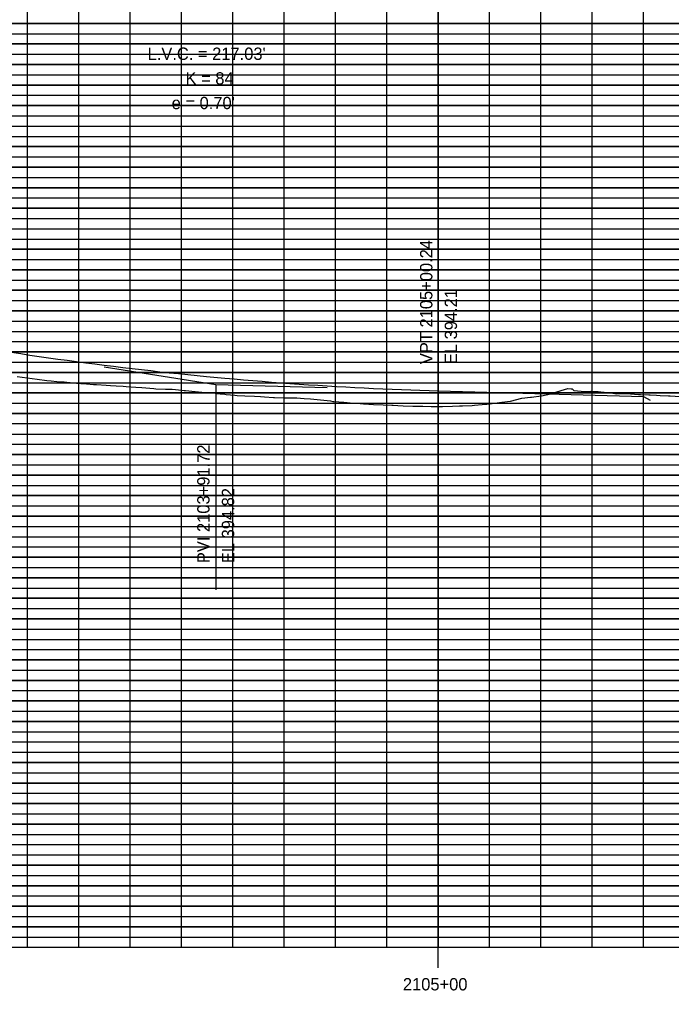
# Model space of a CAD drawing. Extents: x 1195880 to 1289360, y 2059330 to 2086925.
# Drawn here: x 1197268.9 to 1197586.5, y 2066770.1 to 2067243.1 of the extents above; entities that cross this region are included whole.
import ezdxf

# ---------------------------------------------------------------- set-up
doc = ezdxf.new("R2010")
doc.units = 0
for name, color, linetype in [('Clip', 7, 'Continuous'), ('Default', 7, 'Continuous'), ('Existing Ground PGL', 7, 'Continuous'), ('Grid', 7, 'Continuous'), ('Grid Lables', 7, 'Continuous'), ('Profile', 7, 'Continuous'), ('Profile Annotation', 7, 'Continuous')]:
    doc.layers.add(name, color=color, linetype=linetype)

msp = doc.modelspace()

# ---------------------------------------------------------------- linework, layer by layer
at = {"layer": 'Clip'}
msp.add_lwpolyline([(1197072.8, 2066891.15), (1197672.8, 2066891.15), (1197672.8, 2067241.15), (1197072.8, 2067241.15)], close=True, dxfattribs=at)
at = {"layer": 'Default'}
for p, q in [((1197473.04, 2066791.15), (1197473.04, 2067414.26)), ((1197572.8, 2066791.15), (1197572.8, 2067060.45)), ((1197572.8, 2067059.39), (1197576.01, 2067057.62)), ((1197472.8, 2066791.15), (1197473.04, 2066791.15)), ((1197472.8, 2066791.15), (1197572.8, 2066791.15))]:
    msp.add_line(p, q, dxfattribs=at)
at = {"layer": 'Existing Ground PGL'}
for points in [[(1197267.87, 2067069.12), (1197270.26, 2067068.88), (1197272.69, 2067068.53), (1197277.51, 2067067.88), (1197282.32, 2067067.26), (1197284.46, 2067067), (1197287.14, 2067066.79), (1197290.73, 2067066.52), (1197291.96, 2067066.41), (1197296.78, 2067066), (1197298.81, 2067065.84), (1197301.59, 2067065.59), (1197305.08, 2067065.3), (1197306.41, 2067065.21), (1197311.23, 2067064.91), (1197313.26, 2067064.79), (1197316.04, 2067064.61), (1197319.54, 2067064.4), (1197320.86, 2067064.31), (1197325.68, 2067064.02), (1197328.62, 2067063.87), (1197330.5, 2067063.66), (1197334.32, 2067063.26), (1197335.31, 2067063.21), (1197340.13, 2067063.03), (1197343.31, 2067062.94), (1197344.95, 2067062.79), (1197349.21, 2067062.43), (1197349.76, 2067062.37), (1197354.58, 2067061.87), (1197359.4, 2067061.41), (1197364.22, 2067060.98), (1197364.48, 2067060.95), (1197369.03, 2067060.5), (1197369.67, 2067060.44), (1197373.85, 2067060.05), (1197374.96, 2067059.95), (1197378.67, 2067059.78), (1197383.48, 2067059.6), (1197386.3, 2067059.51), (1197388.3, 2067059.32), (1197392.67, 2067058.95), (1197393.12, 2067058.94), (1197397.94, 2067058.84), (1197402.75, 2067058.78), (1197403.99, 2067058.77), (1197407.57, 2067058.54), (1197410.75, 2067058.35), (1197412.39, 2067058.17), (1197417.2, 2067057.67), (1197420.44, 2067057.35), (1197421.64, 2067057.06), (1197422.02, 2067057.02), (1197426.84, 2067056.61), (1197431.66, 2067056.22), (1197433.22, 2067056.11), (1197436.47, 2067055.86), (1197436.81, 2067055.84), (1197441.29, 2067055.59), (1197446.11, 2067055.36), (1197450.22, 2067055.18), (1197450.93, 2067055.14), (1197453.14, 2067055.04), (1197455.74, 2067054.9), (1197455.85, 2067054.9), (1197460.56, 2067054.76), (1197465.38, 2067054.65), (1197469.44, 2067054.58), (1197470.19, 2067054.56), (1197472.06, 2067054.51), (1197475.01, 2067054.59), (1197479.83, 2067054.74), (1197483.25, 2067054.88), (1197484.21, 2067054.81), (1197484.65, 2067054.83), (1197489.46, 2067055.13), (1197490.54, 2067055.2), (1197494.28, 2067055.55), (1197496.48, 2067055.77), (1197496.52, 2067055.77), (1197496.55, 2067055.78), (1197496.61, 2067055.78), (1197496.68, 2067055.79), (1197496.75, 2067055.8), (1197496.83, 2067055.8), (1197496.91, 2067055.81), (1197496.99, 2067055.82), (1197497.09, 2067055.83), (1197497.14, 2067055.84), (1197497.19, 2067055.84), (1197497.28, 2067055.85), (1197497.39, 2067055.86), (1197497.51, 2067055.87), (1197497.53, 2067055.87), (1197497.63, 2067055.88), (1197497.73, 2067055.89), (1197497.8, 2067055.9), (1197497.9, 2067055.91), (1197498.05, 2067055.92), (1197498.12, 2067055.93), (1197498.21, 2067055.94), (1197499.1, 2067056.05), (1197503.91, 2067056.66), (1197508.09, 2067057.2)], [(1197508.09, 2067057.2), (1197513.55, 2067058.59), (1197517.85, 2067059.08), (1197518.37, 2067059.15), (1197522.97, 2067059.75), (1197523.18, 2067059.8), (1197527.75, 2067060.81), (1197528, 2067060.89), (1197532.82, 2067062.38), (1197535.99, 2067063.36), (1197537.63, 2067063.24), (1197538.08, 2067063.21), (1197538.92, 2067062.41), (1197542.45, 2067062.08), (1197544.53, 2067061.88), (1197547.27, 2067061.98), (1197547.39, 2067061.98), (1197550.81, 2067061.8), (1197552.09, 2067061.67), (1197556.9, 2067061.17), (1197557.13, 2067061.15), (1197559.66, 2067060.78), (1197561.72, 2067060.84), (1197562.87, 2067060.88), (1197566.54, 2067060.69), (1197570.37, 2067060.49), (1197571.35, 2067060.45), (1197575.36, 2067060.27), (1197576.17, 2067060.22), (1197579.16, 2067060.03), (1197580.99, 2067059.95), (1197584.95, 2067059.79), (1197585.81, 2067059.75), (1197590.62, 2067059.51)]]:
    msp.add_lwpolyline(points, dxfattribs=at)
at = {"layer": 'Grid'}
for p, q in [((1197272.8, 2066791.15), (1197272.8, 2067391.15)), ((1197297.8, 2066791.15), (1197297.8, 2067391.15)), ((1197322.8, 2066791.15), (1197322.8, 2067391.15)), ((1197347.8, 2066791.15), (1197347.8, 2067391.15)), ((1197372.8, 2066791.15), (1197372.8, 2067391.15)), ((1197397.8, 2066791.15), (1197397.8, 2067391.15)), ((1197422.8, 2066791.15), (1197422.8, 2067391.15)), ((1197447.8, 2066791.15), (1197447.8, 2067391.15)), ((1197472.8, 2066791.15), (1197472.8, 2067391.15)), ((1197497.8, 2066791.15), (1197497.8, 2067391.15)), ((1197522.8, 2066791.15), (1197522.8, 2067391.15)), ((1197547.8, 2066791.15), (1197547.8, 2067391.15)), ((1197572.8, 2066791.15), (1197572.8, 2067391.15)), ((1196972.8, 2067241.15), (1197972.8, 2067241.15)), ((1196972.8, 2067236.15), (1197972.8, 2067236.15)), ((1196972.8, 2067231.15), (1197972.8, 2067231.15)), ((1197972.8, 2067231.15), (1196972.8, 2067231.15)), ((1196972.8, 2067226.15), (1197972.8, 2067226.15)), ((1196972.8, 2067221.15), (1197972.8, 2067221.15)), ((1197972.8, 2067221.15), (1196972.8, 2067221.15)), ((1196972.8, 2067216.15), (1197972.8, 2067216.15)), ((1196972.8, 2067211.15), (1197972.8, 2067211.15)), ((1197972.8, 2067211.15), (1196972.8, 2067211.15)), ((1196972.8, 2067206.15), (1197972.8, 2067206.15)), ((1196972.8, 2067201.15), (1197972.8, 2067201.15)), ((1197972.8, 2067201.15), (1196972.8, 2067201.15)), ((1196972.8, 2067196.15), (1197972.8, 2067196.15)), ((1196972.8, 2067191.15), (1197972.8, 2067191.15)), ((1196972.8, 2067186.15), (1197972.8, 2067186.15)), ((1196972.8, 2067181.15), (1197972.8, 2067181.15)), ((1197972.8, 2067181.15), (1196972.8, 2067181.15)), ((1196972.8, 2067176.15), (1197972.8, 2067176.15)), ((1196972.8, 2067171.15), (1197972.8, 2067171.15)), ((1197972.8, 2067171.15), (1196972.8, 2067171.15)), ((1196972.8, 2067166.15), (1197972.8, 2067166.15)), ((1196972.8, 2067161.15), (1197972.8, 2067161.15)), ((1197972.8, 2067161.15), (1196972.8, 2067161.15)), ((1196972.8, 2067156.15), (1197972.8, 2067156.15)), ((1196972.8, 2067151.15), (1197972.8, 2067151.15)), ((1197972.8, 2067151.15), (1196972.8, 2067151.15)), ((1196972.8, 2067146.15), (1197972.8, 2067146.15)), ((1196972.8, 2067141.15), (1197972.8, 2067141.15)), ((1196972.8, 2067136.15), (1197972.8, 2067136.15)), ((1196972.8, 2067131.15), (1197972.8, 2067131.15)), ((1197972.8, 2067131.15), (1196972.8, 2067131.15)), ((1196972.8, 2067126.15), (1197972.8, 2067126.15)), ((1196972.8, 2067121.15), (1197972.8, 2067121.15)), ((1197972.8, 2067121.15), (1196972.8, 2067121.15)), ((1196972.8, 2067116.15), (1197972.8, 2067116.15)), ((1196972.8, 2067111.15), (1197972.8, 2067111.15)), ((1197972.8, 2067111.15), (1196972.8, 2067111.15)), ((1196972.8, 2067106.15), (1197972.8, 2067106.15)), ((1196972.8, 2067101.15), (1197972.8, 2067101.15)), ((1197972.8, 2067101.15), (1196972.8, 2067101.15)), ((1196972.8, 2067096.15), (1197972.8, 2067096.15)), ((1196972.8, 2067091.15), (1197972.8, 2067091.15)), ((1196972.8, 2067086.15), (1197972.8, 2067086.15)), ((1196972.8, 2067081.15), (1197972.8, 2067081.15)), ((1197972.8, 2067081.15), (1196972.8, 2067081.15)), ((1196972.8, 2067076.15), (1197972.8, 2067076.15)), ((1196972.8, 2067071.15), (1197972.8, 2067071.15)), ((1197972.8, 2067071.15), (1196972.8, 2067071.15)), ((1196972.8, 2067066.15), (1197972.8, 2067066.15)), ((1196972.8, 2067061.15), (1197972.8, 2067061.15)), ((1197972.8, 2067061.15), (1196972.8, 2067061.15)), ((1196972.8, 2067056.15), (1197972.8, 2067056.15)), ((1196972.8, 2067051.15), (1197972.8, 2067051.15)), ((1197972.8, 2067051.15), (1196972.8, 2067051.15)), ((1197972.8, 2067046.15), (1196972.8, 2067046.15)), ((1196972.8, 2067041.15), (1197972.8, 2067041.15)), ((1196972.8, 2067036.15), (1197972.8, 2067036.15)), ((1196972.8, 2067031.15), (1197972.8, 2067031.15)), ((1197972.8, 2067031.15), (1196972.8, 2067031.15)), ((1196972.8, 2067026.15), (1197972.8, 2067026.15)), ((1196972.8, 2067021.15), (1197972.8, 2067021.15)), ((1197972.8, 2067021.15), (1196972.8, 2067021.15)), ((1196972.8, 2067016.15), (1197972.8, 2067016.15)), ((1196972.8, 2067011.15), (1197972.8, 2067011.15)), ((1197972.8, 2067011.15), (1196972.8, 2067011.15)), ((1196972.8, 2067006.15), (1197972.8, 2067006.15)), ((1196972.8, 2067001.15), (1197972.8, 2067001.15)), ((1197972.8, 2067001.15), (1196972.8, 2067001.15)), ((1196972.8, 2066996.15), (1197972.8, 2066996.15)), ((1196972.8, 2066991.15), (1197972.8, 2066991.15)), ((1196972.8, 2066986.15), (1197972.8, 2066986.15)), ((1196972.8, 2066981.15), (1197972.8, 2066981.15)), ((1197972.8, 2066981.15), (1196972.8, 2066981.15)), ((1196972.8, 2066976.15), (1197972.8, 2066976.15)), ((1196972.8, 2066971.15), (1197972.8, 2066971.15)), ((1197972.8, 2066971.15), (1196972.8, 2066971.15)), ((1196972.8, 2066966.15), (1197972.8, 2066966.15)), ((1196972.8, 2066961.15), (1197972.8, 2066961.15)), ((1197972.8, 2066961.15), (1196972.8, 2066961.15)), ((1196972.8, 2066956.15), (1197972.8, 2066956.15)), ((1196972.8, 2066951.15), (1197972.8, 2066951.15)), ((1197972.8, 2066951.15), (1196972.8, 2066951.15)), ((1196972.8, 2066946.15), (1197972.8, 2066946.15)), ((1196972.8, 2066941.15), (1197972.8, 2066941.15)), ((1196972.8, 2066936.15), (1197972.8, 2066936.15)), ((1196972.8, 2066931.15), (1197972.8, 2066931.15)), ((1197972.8, 2066931.15), (1196972.8, 2066931.15)), ((1196972.8, 2066926.15), (1197972.8, 2066926.15)), ((1196972.8, 2066921.15), (1197972.8, 2066921.15)), ((1197972.8, 2066921.15), (1196972.8, 2066921.15)), ((1196972.8, 2066916.15), (1197972.8, 2066916.15)), ((1196972.8, 2066911.15), (1197972.8, 2066911.15)), ((1197972.8, 2066911.15), (1196972.8, 2066911.15)), ((1196972.8, 2066906.15), (1197972.8, 2066906.15)), ((1196972.8, 2066901.15), (1197972.8, 2066901.15)), ((1197972.8, 2066901.15), (1196972.8, 2066901.15)), ((1196972.8, 2066896.15), (1197972.8, 2066896.15)), ((1196972.8, 2066891.15), (1197972.8, 2066891.15)), ((1196972.8, 2066886.15), (1197972.8, 2066886.15)), ((1196972.8, 2066881.15), (1197972.8, 2066881.15)), ((1197972.8, 2066881.15), (1196972.8, 2066881.15)), ((1196972.8, 2066876.15), (1197972.8, 2066876.15)), ((1196972.8, 2066871.15), (1197972.8, 2066871.15)), ((1197972.8, 2066871.15), (1196972.8, 2066871.15)), ((1196972.8, 2066866.15), (1197972.8, 2066866.15)), ((1196972.8, 2066861.15), (1197972.8, 2066861.15)), ((1197972.8, 2066861.15), (1196972.8, 2066861.15)), ((1196972.8, 2066856.15), (1197972.8, 2066856.15)), ((1196972.8, 2066851.15), (1197972.8, 2066851.15)), ((1197972.8, 2066851.15), (1196972.8, 2066851.15)), ((1196972.8, 2066846.15), (1197972.8, 2066846.15)), ((1196972.8, 2066841.15), (1197972.8, 2066841.15)), ((1196972.8, 2066836.15), (1197972.8, 2066836.15)), ((1196972.8, 2066831.15), (1197972.8, 2066831.15)), ((1197972.8, 2066831.15), (1196972.8, 2066831.15)), ((1196972.8, 2066826.15), (1197972.8, 2066826.15)), ((1196972.8, 2066821.15), (1197972.8, 2066821.15)), ((1197972.8, 2066821.15), (1196972.8, 2066821.15)), ((1196972.8, 2066816.15), (1197972.8, 2066816.15)), ((1196972.8, 2066811.15), (1197972.8, 2066811.15)), ((1197972.8, 2066811.15), (1196972.8, 2066811.15)), ((1196972.8, 2066806.15), (1197972.8, 2066806.15)), ((1196972.8, 2066801.15), (1197972.8, 2066801.15)), ((1197972.8, 2066801.15), (1196972.8, 2066801.15)), ((1196972.8, 2066796.15), (1197972.8, 2066796.15)), ((1197272.8, 2066791.15), (1197272.8, 2066794.15)), ((1197297.8, 2066791.15), (1197297.8, 2066794.15)), ((1197322.8, 2066791.15), (1197322.8, 2066794.15)), ((1197347.8, 2066791.15), (1197347.8, 2066794.15)), ((1197372.8, 2066791.15), (1197372.8, 2066794.15)), ((1197397.8, 2066791.15), (1197397.8, 2066794.15)), ((1197422.8, 2066791.15), (1197422.8, 2066794.15)), ((1197447.8, 2066791.15), (1197447.8, 2066794.15)), ((1197497.8, 2066791.15), (1197497.8, 2066794.15)), ((1197522.8, 2066791.15), (1197522.8, 2066794.15)), ((1197547.8, 2066791.15), (1197547.8, 2066794.15)), ((1197572.8, 2066791.15), (1197572.8, 2066794.15)), ((1196972.8, 2066791.15), (1197972.8, 2066791.15)), ((1197472.8, 2066781.15), (1197472.8, 2066791.15))]:
    msp.add_line(p, q, dxfattribs=at)
at = {"layer": 'Profile'}
for q in [(1197473.04, 2067062.21), (1197572.8, 2067059.39)]:
    msp.add_line((1197473.04, 2067062.21), q, dxfattribs=at)
msp.add_lwpolyline([(1197265.05, 2067080.99), (1197269.57, 2067080.31), (1197274.09, 2067079.64), (1197278.61, 2067078.98), (1197283.14, 2067078.34), (1197287.66, 2067077.7), (1197292.18, 2067077.08), (1197296.7, 2067076.47), (1197301.22, 2067075.87), (1197305.74, 2067075.29), (1197310.26, 2067074.71), (1197314.79, 2067074.15), (1197319.31, 2067073.6), (1197323.83, 2067073.07), (1197328.35, 2067072.54), (1197332.87, 2067072.03), (1197337.39, 2067071.53), (1197341.91, 2067071.04), (1197346.44, 2067070.57), (1197350.96, 2067070.11), (1197355.48, 2067069.65), (1197360, 2067069.22), (1197369.04, 2067068.37), (1197373.57, 2067067.97), (1197378.09, 2067067.58), (1197382.61, 2067067.2), (1197387.13, 2067066.84), (1197391.65, 2067066.49), (1197396.17, 2067066.14), (1197400.69, 2067065.81), (1197405.22, 2067065.5), (1197409.74, 2067065.19), (1197414.26, 2067064.9), (1197418.78, 2067064.62), (1197423.3, 2067064.35), (1197427.82, 2067064.1), (1197432.34, 2067063.85), (1197436.87, 2067063.62), (1197441.39, 2067063.4), (1197445.91, 2067063.2), (1197450.43, 2067063), (1197454.95, 2067062.82), (1197459.47, 2067062.65), (1197463.99, 2067062.49), (1197468.52, 2067062.34), (1197473.04, 2067062.21)], dxfattribs=at)
at = {"layer": 'Profile Annotation'}
for p, q in [((1197473.04, 2067062.21), (1197473.04, 2067162.21)), ((1197310.26, 2067073.84), (1197364.52, 2067065.27)), ((1197364.52, 2067065.27), (1197418.78, 2067063.74)), ((1197364.52, 2067065.27), (1197364.52, 2066965.27))]:
    msp.add_line(p, q, dxfattribs=at)

# ---------------------------------------------------------------- texts
at = {"layer": 'Grid Lables'}
msp.add_text('2105+00', height=6, dxfattribs=at).set_placement((1197455.67, 2066770.15))
at = {"layer": 'Profile Annotation'}
for s, p in [("L.V.C. = 217.03'", (1197331.36, 2067223.4)), ('K = 84', (1197349.83, 2067211.4)), ("e = 0.70'", (1197343.07, 2067199.4))]:
    msp.add_text(s, height=6, dxfattribs=at).set_placement(p)
for s, p in [('VPT 2105+00.24', (1197470.04, 2067075.21)), ('EL 394.21', (1197482.04, 2067075.21)), ('PVI 2103+91.72', (1197361.52, 2066978.27)), ('EL 394.82', (1197373.52, 2066978.27))]:
    msp.add_text(s, height=6, rotation=90, dxfattribs=at).set_placement(p)

doc.saveas('drawing.dxf')
